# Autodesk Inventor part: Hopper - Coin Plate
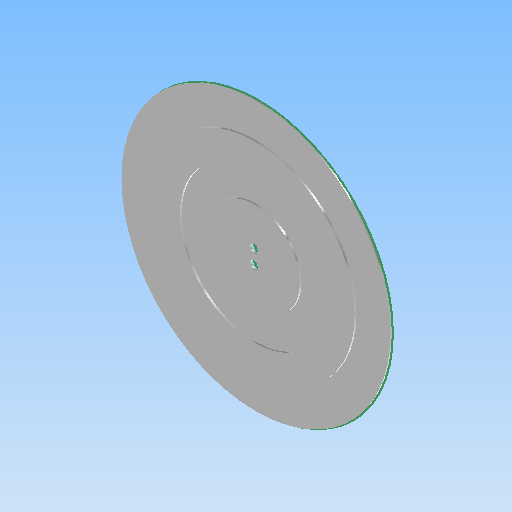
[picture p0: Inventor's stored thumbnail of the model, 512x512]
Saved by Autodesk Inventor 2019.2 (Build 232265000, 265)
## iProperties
Created: 2005-11
Part Number: Hopper - Coin Plate
Document SubType Name: Modeling
Designer: floress
Material: Aluminum 6061
Density: 2.7 g/cm^3
Appearance: Aluminum - Flat
Mass: 36.8496 g
Surface Area: 227.957 cm^2
Volume: 13.648 cm^3
Author: floress
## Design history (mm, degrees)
sketch "Sketch1"
  geometry: C1 r 44.45 at (0, 0); C2 r 1.778 at (0, -3.175); C3 r 1.778 at (0, 3.175); 1 further point
  constraints: 3 centre point, 1 coincident, 1 equal radius
  dimensions: "d0" = 88.9 diameter of C1; "d1" = 3.556 diameter of C2
extrude "Extrusion1" new body sketch "Sketch1" distance "d2" = 0.79375; taper "d3" = 0 deg
sketch "Sketch2"
  geometry: C1 r 59.531 at (0, 0); C2 r 6.35 at (0, 0) reference
  constraints: 1 centre point
  dimensions: "d16" = 119.0625 diameter of C1
extrude "Extrusion2" join sketch "Sketch2" distance "d5" = 0.79375; taper "d6" = 0 deg
sketch "Sketch4"
  geometry: C1 r 1.778 at (0, 3.175) reference; C2 r 1.778 at (0, -3.175) reference; C3 r 44.45 at (0, 0) reference; C4 r 32.873 at (0, 0); C5 r 20.173 at (0, 0); 1 further point
  constraints: 2 centre point
  dimensions: "d17" = 12.7 radial gap between concentric circles of C4 C5
extrude "Extrusion4" cut sketch "Sketch4" distance "d18" = 1.5875; taper "d19" = 0 deg
sketch "Sketch5"
  geometry: C1 r 59.531 at (0, 0) reference; C2 r 1.778 at (0, 3.175) reference; C3 r 1.778 at (0, -3.175) reference; 1 further point
sketch "Sketch3"
  geometry: C1 r 0.794 at (0, 53.907); C2 r 0.794 at (-18.437, 50.656); C3 r 0.794 at (-34.651, 41.295); C4 r 0.794 at (-46.685, 26.954); C5 r 0.794 at (-53.088, 9.361); C6 r 0.794 at (-53.088, -9.361); C7 r 0.794 at (-46.685, -26.954); C8 r 0.794 at (-34.651, -41.295); C9 r 0.794 at (-18.437, -50.656); C10 r 0.794 at (0, -53.907); C11 r 0.794 at (18.437, -50.656); C12 r 0.794 at (34.651, -41.295); C13 r 0.794 at (46.685, -26.954); C14 r 0.794 at (53.088, -9.361); C15 r 0.794 at (53.088, 9.361); C16 r 0.794 at (46.685, 26.954); C17 r 0.794 at (34.651, 41.295); C18 r 0.794 at (18.437, 50.656); 2 further points
  constraints: 18 centre point, 1 coincident, 1 vertical alignment, 37 other
  dimensions: "d12" = 360 deg dimension on point (0, 0) C1.centre (derived)
extrude "Extrusion3" join sketch "Sketch3" distance "d14" = 4.7625; taper "d15" = 0 deg
body "Solid1"
node "Reference4"
node "Projected Loop2"
other parameters: "NestingThickness" = 1.5875
